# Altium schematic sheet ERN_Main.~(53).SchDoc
size A; SheetNumber: 1; SheetTotal: 3; SPICEModelCacheDBTNACQE: <root> / <DocumentId>DBTNACQE</DocumentId> / </root>
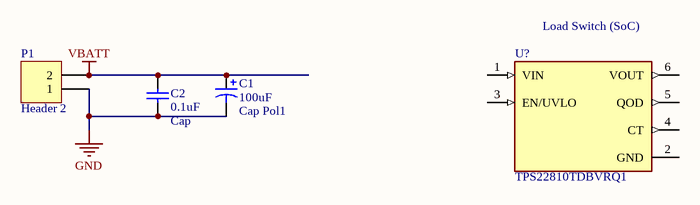
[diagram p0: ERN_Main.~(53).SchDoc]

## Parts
C1  Cap Pol1  value 100uF  [RB7.6-15]
C2  Cap  value 0.1uF  [RAD-0.3]
P1  Header 2  [HDR1X2]
U?  TPS22810TDBVRQ1  [SOT95P280X145-6N]

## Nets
GND: C1.2 C2.1 P1.1
VBATT: C1.1 C2.2 P1.2

Not connected (* = marked no-connect by the designer): U? 1(VIN) 2(GND) 3(EN/UVLO) 4(CT) 5(QOD) 6(VOUT)

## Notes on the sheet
- (near U?) Load Switch (SoC)

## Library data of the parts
C1 = Cap Pol1: Polarized Capacitor (Radial)
C2 = Cap: Capacitor
P1 = Header 2: Header, 2-Pin
U? = TPS22810TDBVRQ1: Automotive 1-channel, 18-V, 2-A, 79-mâ„¦ load switch with adj. rise time and adj. output discharge; MF: Texas Instruments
